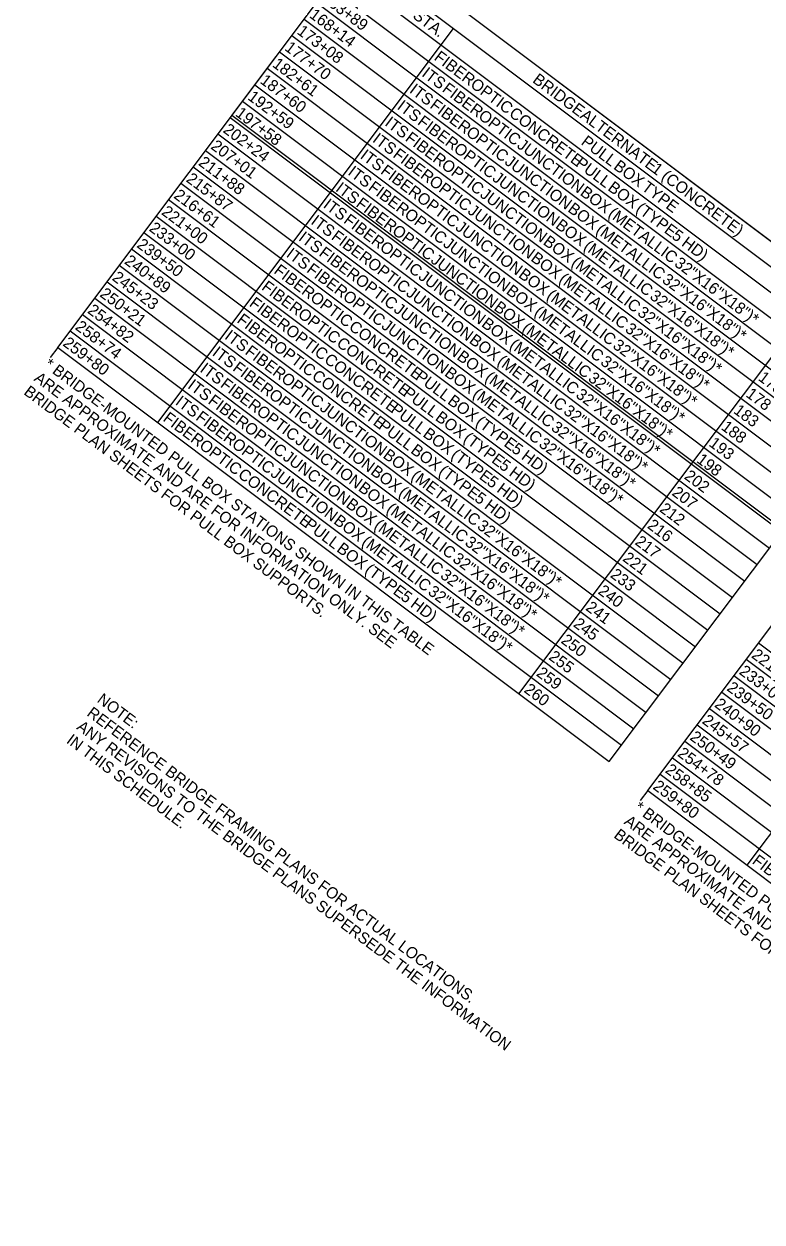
# Model space of a CAD drawing. Extents: x 626494 to 629419, y 365986 to 369334.
# Drawn here: x 627788.4 to 628055, y 367961.6 to 368394.1 of the extents above; entities that cross this region are included whole.
import ezdxf

# ---------------------------------------------------------------- set-up
doc = ezdxf.new("R2010")
doc.units = 0
for name, color, linetype in [('Default', 7, 'Continuous'), ('R_Grid_SCR50', 7, 'Continuous'), ('R_No Plot', 7, 'Continuous')]:
    doc.layers.add(name, color=color, linetype=linetype)

msp = doc.modelspace()

# ---------------------------------------------------------------- linework, layer by layer
at = {"layer": 'Default'}
for p, q in [((627800.61, 368277.33), (627911.88, 368425.51)), ((627911.88, 368425.51), (628111.03, 368275.96)), ((627907.43, 368419.58), (628106.58, 368270.04)), ((627902.97, 368413.65), (628102.13, 368264.11)), ((627898.52, 368407.73), (628097.68, 368258.18)), ((627894.07, 368401.8), (628093.22, 368252.26)), ((627889.62, 368395.87), (628088.77, 368246.33)), ((627836.76, 368250.18), (627943.58, 368392.43)), ((627885.17, 368389.95), (628084.32, 368240.4)), ((627880.72, 368384.02), (628079.87, 368234.47)), ((627876.27, 368378.09), (628075.42, 368228.55)), ((627871.82, 368372.16), (628070.97, 368222.62)), ((627867.37, 368366.24), (628066.52, 368216.69)), ((627862.92, 368360.31), (628062.07, 368210.77)), ((627858.47, 368354.38), (628057.62, 368204.84)), ((627854.02, 368348.46), (628053.17, 368198.91)), ((627849.57, 368342.53), (628048.72, 368192.98)), ((627845.11, 368336.6), (628044.27, 368187.06)), ((627840.66, 368330.67), (628039.82, 368181.13)), ((627836.21, 368324.75), (628035.36, 368175.2)), ((627831.76, 368318.82), (628030.91, 368169.28)), ((627827.31, 368312.89), (628026.46, 368163.35)), ((627822.86, 368306.97), (628022.01, 368157.42)), ((627818.41, 368301.04), (628017.56, 368151.49)), ((627813.96, 368295.11), (628013.11, 368145.57)), ((627967.16, 368152.27), (628073.98, 368294.52)), ((627809.51, 368289.18), (628008.66, 368139.64)), ((627805.06, 368283.26), (628004.21, 368133.71)), ((627800.61, 368277.33), (627999.76, 368127.79)), ((627999.76, 368127.79), (628111.03, 368275.96)), ((627999.76, 368127.79), (628111.03, 368275.96)), ((628013.69, 368117.33), (628124.96, 368265.5)), ((628013.69, 368117.33), (628124.96, 368265.5)), ((628049.55, 368090.4), (628156.36, 368232.65)), ((628053.74, 368170.67), (628261.19, 368014.9)), ((628049.29, 368164.74), (628256.74, 368008.97)), ((628044.84, 368158.82), (628252.29, 368003.04)), ((628040.39, 368152.89), (628247.84, 367997.11)), ((628035.94, 368146.96), (628243.39, 367991.19)), ((628031.49, 368141.04), (628238.94, 367985.26)), ((628027.04, 368135.11), (628234.49, 367979.33)), ((628022.59, 368129.18), (628230.04, 367973.41)), ((628018.14, 368123.25), (628225.59, 367967.48)), ((628013.69, 368117.33), (628221.14, 367961.55))]:
    msp.add_line(p, q, dxfattribs=at)
at = {"layer": 'R_No Plot'}
for p, q in [((627800.61, 368277.33), (627797.91, 368273.73)), ((628013.69, 368117.33), (628010.99, 368113.73))]:
    msp.add_line(p, q, dxfattribs=at)
msp.add_lwpolyline([(627911.88, 368425.51), (628234.33, 368183.37), (628185.91, 368118.88), (627863.45, 368361.02)], close=True, dxfattribs=at)

# ---------------------------------------------------------------- texts
at = {"layer": 'Default'}
for s, height, p in [('163+89', 4.181, (627895.64, 368402.65)), ('168+14', 4.181, (627891.18, 368396.72)), (' STA.', 4.181, (627927.26, 368397.44)), ('173+08', 4.181, (627886.73, 368390.79)), ('177+70', 4.181, (627882.28, 368384.87)), ('182+61', 4.181, (627877.83, 368378.94)), ('FIBER', 4.181, (627936.24, 368381.42)), ('ITS', 4.181, (627931.79, 368375.5)), ('187+60', 4.181, (627873.38, 368373.01)), ('ITS', 4.181, (627927.34, 368369.57)), (' FIBER', 4.181, (627937.92, 368370.9)), (' OPTIC', 4.181, (627948.09, 368372.53)), ('BRIDGE', 4.181, (627971.79, 368373.27)), ('192+59', 4.181, (627868.93, 368367.08)), ('ITS', 4.181, (627922.89, 368363.64)), (' FIBER', 4.181, (627933.47, 368364.97)), (' CONCRETE', 4.181, (627962.05, 368362.04)), ('197+58', 4.181, (627864.48, 368361.16)), ('ITS', 4.181, (627918.44, 368357.72)), (' FIBER', 4.181, (627929.01, 368359.04)), (' OPTIC', 4.181, (627950.95, 368361.11)), (' ALTERNATE', 4.181, (627987.7, 368361.32)), ('202+24', 4.181, (627860.03, 368355.23)), (' FIBER', 4.181, (627924.56, 368353.12)), (' OPTIC', 4.181, (627946.5, 368355.18)), ('207+01', 4.181, (627855.58, 368349.3)), ('ITS', 4.181, (627913.99, 368351.79)), (' OPTIC', 4.181, (627942.05, 368349.25)), (' JUNCTION', 4.181, (627964.92, 368350.62)), ('PULL', 4.181, (627989.31, 368350.85)), ('ITS', 4.181, (627909.54, 368345.86)), (' FIBER', 4.181, (627920.11, 368347.19)), (' JUNCTION', 4.181, (627960.46, 368344.7)), ('211+88', 4.181, (627851.13, 368343.38)), ('ITS', 4.181, (627905.09, 368339.93)), (' FIBER', 4.181, (627915.66, 368341.26)), (' OPTIC', 4.181, (627937.6, 368343.33)), (' PULL', 4.181, (627986.04, 368344.03)), (' BOX', 4.181, (627999.79, 368342.97)), (' 1', 4.181, (628013.46, 368341.98)), ('215+87', 4.181, (627846.68, 368337.45)), (' OPTIC', 4.181, (627933.15, 368337.4)), (' JUNCTION', 4.181, (627956.01, 368338.77)), (' (CONCRETE)', 4.1812, (628017.04, 368339.29)), ('216+61', 4.181, (627842.23, 368331.52)), ('ITS', 4.181, (627900.64, 368334.01)), (' FIBER', 4.181, (627911.21, 368335.34)), (' JUNCTION', 4.181, (627951.56, 368332.84)), (' BOX', 4.181, (627987.72, 368333.5)), (' BOX', 4.181, (627997.72, 368335.26)), (' TYPE', 4.181, (628009.95, 368335.35)), ('ITS', 4.181, (627896.19, 368328.08)), (' FIBER', 4.181, (627906.76, 368329.41)), (' OPTIC', 4.181, (627928.7, 368331.47)), (' BOX', 4.181, (627983.27, 368327.58)), (' (TYPE', 4.181, (628007.87, 368327.64)), ('221+00', 4.181, (627837.78, 368325.59)), ('ITS', 4.181, (627891.73, 368322.15)), (' FIBER', 4.181, (627902.31, 368323.48)), (' OPTIC', 4.181, (627924.25, 368325.55)), (' JUNCTION', 4.181, (627947.11, 368326.92)), (' (METALLIC', 4.181, (627997.87, 368325.88)), ('233+00', 4.181, (627833.33, 368319.67)), (' OPTIC', 4.181, (627919.8, 368319.62)), (' JUNCTION', 4.181, (627942.66, 368320.99)), (' BOX', 4.181, (627978.82, 368321.65)), (' (METALLIC', 4.181, (627993.42, 368319.95)), ('239+50', 4.181, (627828.87, 368313.74)), ('ITS', 4.181, (627887.28, 368316.23)), (' FIBER', 4.181, (627897.86, 368317.55)), (' JUNCTION', 4.181, (627938.21, 368315.06)), (' BOX', 4.181, (627974.36, 368315.72)), (' 5', 4.181, (628020.81, 368317.92)), (' HD)', 4.181, (628024.36, 368315.25)), ('ITS', 4.181, (627882.83, 368310.3)), (' FIBER', 4.181, (627893.41, 368311.63)), (' OPTIC', 4.181, (627915.35, 368313.69)), (' BOX', 4.181, (627969.91, 368309.79)), (' (METALLIC', 4.181, (627988.97, 368314.02)), ('240+89', 4.181, (627824.42, 368307.81)), ('FIBER', 4.181, (627878.38, 368304.37)), (' FIBER', 4.181, (627888.96, 368305.7)), (' OPTIC', 4.181, (627910.9, 368307.76)), (' JUNCTION', 4.181, (627933.76, 368309.13)), (' (METALLIC', 4.181, (627984.52, 368308.1)), (' 32"X16"X18")*', 4.1812, (628021.77, 368307.93)), ('245+23', 4.181, (627819.97, 368301.89)), (' OPTIC', 4.181, (627906.45, 368301.84)), (' JUNCTION', 4.181, (627929.31, 368303.21)), (' BOX', 4.181, (627965.46, 368303.87)), (' (METALLIC', 4.181, (627980.07, 368302.17)), (' 32"X16"X18")*', 4.1812, (628017.32, 368302)), ('FIBER', 4.181, (627873.93, 368298.44)), (' JUNCTION', 4.181, (627924.86, 368297.28)), (' BOX', 4.181, (627961.01, 368297.94)), ('250+21', 4.181, (627815.52, 368295.96)), ('FIBER', 4.181, (627869.48, 368292.52)), (' OPTIC', 4.181, (627890.23, 368295.48)), (' OPTIC', 4.181, (627902, 368295.91)), (' (METALLIC', 4.181, (627975.62, 368296.24)), (' 32"X16"X18")*', 4.1812, (628012.87, 368296.08)), ('254+82', 4.181, (627811.07, 368290.03)), (' OPTIC', 4.181, (627885.78, 368289.55)), (' JUNCTION', 4.181, (627920.41, 368291.35)), (' BOX', 4.181, (627956.56, 368292.01)), (' (METALLIC', 4.181, (627971.17, 368290.32)), (' 32"X16"X18")*', 4.1812, (628008.42, 368290.15)), ('258+74', 4.181, (627806.62, 368284.1)), ('FIBER', 4.181, (627865.03, 368286.59)), (' CONCRETE', 4.181, (627904.19, 368284.99)), (' JUNCTION', 4.181, (627915.96, 368285.43)), (' BOX', 4.181, (627952.11, 368286.09)), (' (METALLIC', 4.181, (627966.72, 368284.39)), (' 32"X16"X18")*', 4.1812, (628003.97, 368284.22)), ('ITS', 4.181, (627860.58, 368280.66)), (' OPTIC', 4.181, (627881.33, 368283.62)), (' BOX', 4.181, (627947.66, 368280.16)), ('259+80', 4.181, (627802.17, 368278.18)), ('ITS', 4.181, (627856.13, 368274.74)), (' FIBER', 4.181, (627866.7, 368276.06)), (' OPTIC', 4.181, (627876.88, 368277.69)), (' CONCRETE', 4.181, (627899.74, 368279.06)), (' (METALLIC', 4.181, (627962.26, 368278.46)), (' 32"X16"X18")*', 4.1812, (627999.52, 368278.3)), (' CONCRETE', 4.181, (627895.29, 368273.14)), (' BOX', 4.181, (627943.21, 368274.23)), (' (METALLIC', 4.181, (627957.81, 368272.53)), (' 32"X16"X18")*', 4.1812, (627995.07, 368272.37)), ('ITS', 4.181, (627851.68, 368268.81)), (' FIBER', 4.181, (627862.25, 368270.14)), (' CONCRETE', 4.181, (627890.84, 368267.21)), (' PULL', 4.181, (627928.18, 368266.98)), (' BOX', 4.181, (627938.76, 368268.3)), ('ITS', 4.181, (627847.23, 368262.88)), (' FIBER', 4.181, (627857.8, 368264.21)), (' OPTIC', 4.181, (627879.74, 368266.27)), (' (METALLIC', 4.181, (627953.36, 368266.61)), (' 32"X16"X18")*', 4.1812, (627990.62, 368266.44)), ('173', 4.181, (628053.29, 368265.73)), ('ITS', 4.181, (627842.78, 368256.96)), (' FIBER', 4.181, (627853.35, 368258.28)), (' OPTIC', 4.181, (627875.29, 368260.35)), (' PULL', 4.181, (627923.73, 368261.05)), (' BOX', 4.181, (627939.86, 368258.21)), (' (METALLIC', 4.181, (627948.91, 368260.68)), (' 32"X16"X18")*', 4.1812, (627986.16, 368260.51)), ('178', 4.181, (628048.84, 368259.8)), (' OPTIC', 4.181, (627870.84, 368254.42)), (' JUNCTION', 4.181, (627893.7, 368255.79)), (' PULL', 4.181, (627919.28, 368255.12)), (' 32"X16"X18")*', 4.1812, (627981.71, 368254.59)), ('183', 4.181, (628044.39, 368253.87)), ('FIBER', 4.181, (627838.33, 368251.03)), (' FIBER', 4.181, (627848.9, 368252.36)), (' JUNCTION', 4.181, (627889.25, 368249.86)), (' PULL', 4.181, (627914.83, 368249.19)), (' BOX', 4.181, (627935.41, 368252.28)), (' (TYPE', 4.181, (627950.01, 368250.58)), (' OPTIC', 4.181, (627866.39, 368248.49)), (' BOX', 4.181, (627930.96, 368246.35)), (' 32"X16"X18")*', 4.1812, (627977.26, 368248.66)), ('188', 4.181, (628039.93, 368247.95)), (' OPTIC', 4.181, (627850.17, 368242.13)), (' OPTIC', 4.181, (627861.94, 368242.57)), (' JUNCTION', 4.181, (627884.8, 368243.94)), (' BOX', 4.181, (627926.51, 368240.43)), (' (TYPE', 4.181, (627945.56, 368244.66)), (' 5', 4.181, (627962.95, 368240.87)), (' 32"X16"X18")*', 4.1812, (627972.81, 368242.73)), ('193', 4.181, (628035.48, 368242.02)), (' JUNCTION', 4.181, (627880.35, 368238.01)), (' BOX', 4.181, (627916.51, 368238.67)), (' (TYPE', 4.181, (627941.11, 368238.73)), (' HD)', 4.181, (627966.5, 368238.2)), ('198', 4.181, (628031.03, 368236.09)), (' BOX', 4.181, (627912.05, 368232.74)), (' (TYPE', 4.181, (627936.66, 368232.8)), (' 5', 4.181, (627958.5, 368234.94)), (' HD)', 4.181, (627962.05, 368232.27)), (' CONCRETE', 4.181, (627864.14, 368231.65)), (' JUNCTION', 4.181, (627875.9, 368232.08)), (' (METALLIC', 4.181, (627926.66, 368231.04)), (' 5', 4.181, (627954.05, 368229.01)), ('202', 4.181, (628026.58, 368230.16)), (' BOX', 4.181, (627907.6, 368226.81)), (' (METALLIC', 4.181, (627922.21, 368225.12)), (' HD)', 4.181, (627957.6, 368226.35)), ('207', 4.181, (628022.13, 368224.24)), (' BOX', 4.181, (627903.15, 368220.89)), (' (METALLIC', 4.181, (627917.76, 368219.19)), (' 5', 4.181, (627949.6, 368223.09)), (' HD)', 4.181, (627953.15, 368220.42)), ('212', 4.181, (628017.68, 368218.31)), (' BOX', 4.181, (627898.7, 368214.96)), (' PULL', 4.181, (627888.13, 368213.63)), (' (METALLIC', 4.181, (627913.31, 368213.26)), (' 32"X16"X18")*', 4.1812, (627950.56, 368213.1)), ('216', 4.181, (628013.23, 368212.38)), (' (METALLIC', 4.181, (627908.86, 368207.34)), (' 32"X16"X18")*', 4.1812, (627946.11, 368207.17)), ('217', 4.181, (628008.78, 368206.46)), (' BOX', 4.181, (627899.8, 368204.86)), (' 32"X16"X18")*', 4.1812, (627941.66, 368201.24)), ('221', 4.181, (628004.33, 368200.53)), (' (TYPE', 4.181, (627909.96, 368197.24)), (' 32"X16"X18")*', 4.1812, (627937.21, 368195.32)), ('233', 4.181, (627999.88, 368194.6)), (' 32"X16"X18")*', 4.1812, (627932.76, 368189.39)), ('240', 4.181, (627995.43, 368188.67)), (' 5', 4.181, (627922.9, 368187.52)), (' HD)', 4.181, (627926.45, 368184.86)), ('241', 4.181, (627990.98, 368182.75)), ('245', 4.181, (627986.53, 368176.82)), ('250', 4.181, (627982.07, 368170.89)), ('255', 4.181, (627977.62, 368164.97)), ('221+00', 4.181, (628050.86, 368165.59)), ('259', 4.181, (627973.17, 368159.04)), ('233+00', 4.181, (628046.41, 368159.66)), ('239+50', 4.181, (628041.95, 368153.74)), ('260', 4.181, (627968.72, 368153.11)), ('240+90', 4.181, (628037.5, 368147.81)), ('245+57', 4.181, (628033.05, 368141.88)), ('250+49', 4.181, (628028.6, 368135.95)), ('254+78', 4.181, (628024.15, 368130.03)), ('258+85', 4.181, (628019.7, 368124.1)), ('259+80', 4.181, (628015.25, 368118.17)), ('FIBER', 4.181, (628051.11, 368091.25))]:
    msp.add_text(s, height=height, rotation=323.0968, dxfattribs=at).set_placement(p)
at = {"layer": 'R_Grid_SCR50'}
for s, p in [('* BRIDGE-MOUNTED PULL BOX STATIONS SHOWN IN THIS TABLE', (627795.44, 368270.45)), ('ARE APPROXIMATE AND ARE FOR INFORMATION ONLY. SEE', (627791.75, 368265.54)), ('BRIDGE PLAN SHEETS FOR PULL BOX SUPPORTS.', (627788.06, 368260.62)), ('NOTE:', (627814.54, 368149.53)), ('REFERENCE BRIDGE FRAMING PLANS FOR ACTUAL LOCATIONS.', (627810.84, 368144.61)), ('ANY REVISIONS TO THE BRIDGE PLANS SUPERSEDE THE INFORMATION', (627807.15, 368139.69)), ('IN THIS SCHEDULE.', (627803.46, 368134.78)), ('* BRIDGE-MOUNTED PULL BOX STATIONS SHOWN IN THIS TABLE', (628008.52, 368110.45)), ('ARE APPROXIMATE AND ARE FOR INFORMATION ONLY. SEE', (628004.83, 368105.53)), ('BRIDGE PLAN SHEETS FOR PULL BOX SUPPORTS.', (628001.14, 368100.61))]:
    msp.add_text(s, height=4.1, rotation=323.0968, dxfattribs=at).set_placement(p)

doc.saveas('drawing.dxf')
